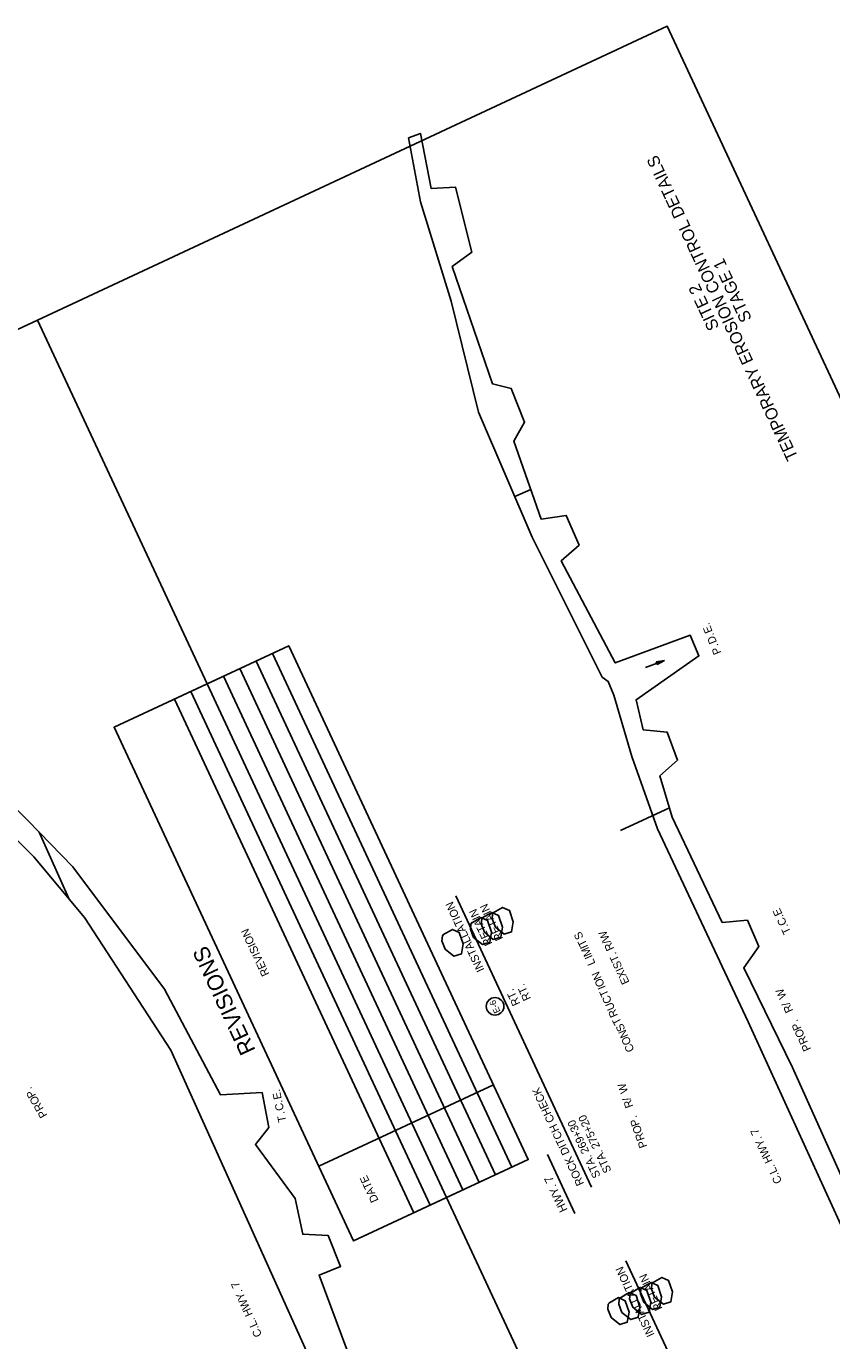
# Model space of a CAD drawing. Extents: x 964229 to 965790, y 1899262 to 1901149.
# Drawn here: x 964635 to 965239, y 1900163 to 1901149 of the extents above; entities that cross this region are included whole.
import ezdxf

# ---------------------------------------------------------------- set-up
doc = ezdxf.new("R2010")
doc.units = 0
for name, color, linetype in [('1', 7, 'Continuous'), ('43', 7, 'Continuous'), ('44', 7, 'Continuous'), ('60', 7, 'Continuous'), ('Default', 7, 'Continuous'), ('NO PLOT', 7, 'Continuous'), ('R_Draft', 7, 'Continuous'), ('R_Horz Alg Annot', 7, 'Continuous'), ('S_TREE', 7, 'Continuous')]:
    doc.layers.add(name, color=color, linetype=linetype)

msp = doc.modelspace()

# ---------------------------------------------------------------- linework, layer by layer
at = {"layer": '1'}
for p, q in [((964770.42, 1900655.58), (964643.21, 1900928.38)), ((965070.98, 1900011.03), (964950.03, 1900270.4))]:
    msp.add_line(p, q, dxfattribs=at)
msp.add_circle((964986.37, 1900413.77), 6.61, dxfattribs=at)
at = {"layer": '43'}
for p, q in [((965107.31, 1900672.01), (965113.37, 1900673.17)), ((965108.07, 1900670.01), (965107.31, 1900672.01)), ((965113.37, 1900673.17), (965108.07, 1900670.01))]:
    msp.add_line(p, q, dxfattribs=at)
msp.add_lwpolyline([(965099.17, 1900667.78), (965113.37, 1900673.17)], dxfattribs=at)
at = {"layer": '44'}
for p, q in [((965058.7, 1900278.13), (964956.85, 1900496.56)), ((965046.31, 1900258.35), (965025.67, 1900302.62)), ((965186.28, 1900004.53), (965084.43, 1900222.96))]:
    msp.add_line(p, q, dxfattribs=at)
at = {"layer": 'Default'}
for p, q in [((964700.63, 1900623.04), (964831.6, 1900684.11)), ((965011.21, 1900298.93), (964831.6, 1900684.11)), ((964986.74, 1900287.52), (964807.12, 1900672.7)), ((964998.97, 1900293.22), (964819.36, 1900678.4)), ((964962.27, 1900276.11), (964782.65, 1900661.29)), ((964962.27, 1900276.11), (964782.65, 1900661.29)), ((964974.5, 1900281.81), (964794.89, 1900666.99)), ((964950.03, 1900270.4), (964770.42, 1900655.58)), ((964925.56, 1900258.99), (964745.95, 1900644.17)), ((964937.8, 1900264.7), (964758.18, 1900649.88)), ((964880.25, 1900237.86), (964700.63, 1900623.04)), ((964854.12, 1900293.88), (964985.09, 1900354.95)), ((964880.25, 1900237.86), (965011.21, 1900298.93))]:
    msp.add_line(p, q, dxfattribs=at)
at = {"layer": 'NO PLOT'}
for points in [[(965789.77, 1899702.74), (965115.54, 1901148.63), (964643.21, 1900928.38), (964770.42, 1900655.58), (964831.6, 1900684.11), (965011.21, 1900298.93), (964950.03, 1900270.4), (965070.98, 1900011.03), (965126.95, 1900037.14), (965271.77, 1899726.58), (965215.79, 1899700.48), (965317.44, 1899482.49)], [(965789.77, 1899702.74), (965115.54, 1901148.63), (964643.21, 1900928.38), (964770.42, 1900655.58), (964831.6, 1900684.11), (965011.21, 1900298.93), (964950.03, 1900270.4), (965070.98, 1900011.03), (965126.95, 1900037.14), (965271.77, 1899726.58), (965215.79, 1899700.48), (965317.44, 1899482.49)], [(965789.77, 1899702.74), (965115.54, 1901148.63), (964643.21, 1900928.38), (964770.42, 1900655.58), (964831.6, 1900684.11), (965011.21, 1900298.93), (964950.03, 1900270.4), (965070.98, 1900011.03), (965126.95, 1900037.14), (965271.77, 1899726.58), (965215.79, 1899700.48), (965317.44, 1899482.49)], [(965789.77, 1899702.74), (965115.54, 1901148.63), (964643.21, 1900928.38), (964770.42, 1900655.58), (964831.6, 1900684.11), (965011.21, 1900298.93), (964950.03, 1900270.4), (965070.98, 1900011.03), (965126.95, 1900037.14), (965271.77, 1899726.58), (965215.79, 1899700.48), (965317.44, 1899482.49)], [(964845.11, 1899262.24), (964344.7, 1900335.36), (964389.48, 1900356.24), (964306.73, 1900533.69), (964319.96, 1900539.86), (964228.89, 1900735.17), (964643.21, 1900928.38), (964770.42, 1900655.58), (964700.63, 1900623.04), (964880.25, 1900237.86), (964950.03, 1900270.4), (965070.98, 1900011.03), (965017.24, 1899985.98), (965162.05, 1899675.42), (965215.79, 1899700.48), (965317.44, 1899482.49)], [(964845.11, 1899262.24), (964344.7, 1900335.36), (964389.48, 1900356.24), (964306.73, 1900533.69), (964319.96, 1900539.86), (964228.89, 1900735.17), (964643.21, 1900928.38), (964770.42, 1900655.58), (964700.63, 1900623.04), (964880.25, 1900237.86), (964950.03, 1900270.4), (965070.98, 1900011.03), (965017.24, 1899985.98), (965162.05, 1899675.42), (965215.79, 1899700.48), (965317.44, 1899482.49)], [(964845.11, 1899262.24), (964344.7, 1900335.36), (964389.48, 1900356.24), (964306.73, 1900533.69), (964319.96, 1900539.86), (964228.89, 1900735.17), (964643.21, 1900928.38), (964770.42, 1900655.58), (964700.63, 1900623.04), (964880.25, 1900237.86), (964950.03, 1900270.4), (965070.98, 1900011.03), (965017.24, 1899985.98), (965162.05, 1899675.42), (965215.79, 1899700.48), (965317.44, 1899482.49)], [(964845.11, 1899262.24), (964344.7, 1900335.36), (964389.48, 1900356.24), (964306.73, 1900533.69), (964319.96, 1900539.86), (964228.89, 1900735.17), (964643.21, 1900928.38), (964770.42, 1900655.58), (964700.63, 1900623.04), (964880.25, 1900237.86), (964950.03, 1900270.4), (965070.98, 1900011.03), (965017.24, 1899985.98), (965162.05, 1899675.42), (965215.79, 1899700.48), (965317.44, 1899482.49)]]:
    msp.add_lwpolyline(points, close=True, dxfattribs=at)
for points in [[(965276.22, 1900219.57), (965209.45, 1900368.04), (965172.94, 1900442.58), (965184.09, 1900458.7), (965175.64, 1900478.35), (965156.73, 1900476.57), (965119.19, 1900555.56), (965110.04, 1900586.51), (965123.23, 1900598.29), (965115.52, 1900619.35), (965097.43, 1900621.13), (965092.19, 1900643.69), (965139.24, 1900676.55), (965132.67, 1900692.15), (965076.52, 1900671.25), (965035.92, 1900747.75), (965049.39, 1900759.67), (965039.71, 1900781.92), (965020.92, 1900779.15), (965000.39, 1900837.54), (965008.5, 1900851.88), (964998.48, 1900877.15), (964984.57, 1900880.52), (964954.14, 1900968.46), (964968.86, 1900979.2), (964956.64, 1901028.08), (964938.47, 1901027), (964930.46, 1901068.35), (964921.51, 1901064.88), (964930.48, 1901016.94), (964953.57, 1900942.48), (964973.99, 1900859.39), (965014.26, 1900765.47), (965066.66, 1900660.66), (965071.22, 1900657.42), (965075.39, 1900647.12), (965088.99, 1900601.01), (965108.1, 1900546.87), (965176.25, 1900402.21), (965291.71, 1900149.32)], [(964559.33, 1900606.42), (964640.41, 1900525.78), (964678.6, 1900480.49), (964743.2, 1900380.79), (964921.35, 1899985.44)], [(964905.36, 1900075.22), (964854.38, 1900212.3), (964870.5, 1900218.78), (964861.28, 1900241.9), (964842.21, 1900242.83), (964836.44, 1900269.62), (964806.72, 1900310.07), (964816.72, 1900323.01), (964811.78, 1900349.15), (964780.47, 1900347.49), (964738.38, 1900426.65), (964669.78, 1900518.27), (964635.92, 1900553.17), (964585.88, 1900602.76)]]:
    msp.add_lwpolyline(points, dxfattribs=at)
at = {"layer": 'R_Horz Alg Annot'}
msp.add_line((964644.4, 1900544.42), (964666.65, 1900494.66), dxfattribs=at)
for points in [[(965001.15, 1900796.05), (965013.11, 1900801.36)], [(965080.56, 1900545.69), (965117.09, 1900562.69)]]:
    msp.add_lwpolyline(points, dxfattribs=at)
at = {"layer": 'S_TREE'}
for points in [[(964976.78, 1900480.04), (964983.92, 1900484.16), (964988.97, 1900481.86), (964991.88, 1900473.25), (964990.6, 1900465.73), (964985.03, 1900463.96), (964978.46, 1900469.3), (964976.05, 1900475.55), (964976.34, 1900479.25), (964977.42, 1900480.57)], [(964976.78, 1900480.04), (964983.92, 1900484.16), (964988.97, 1900481.86), (964991.88, 1900473.25), (964990.6, 1900465.73), (964985.03, 1900463.96), (964978.46, 1900469.3), (964976.05, 1900475.55), (964976.34, 1900479.25), (964977.42, 1900480.57)], [(964976.78, 1900480.04), (964983.92, 1900484.16), (964988.97, 1900481.86), (964991.88, 1900473.25), (964990.6, 1900465.73), (964985.03, 1900463.96), (964978.46, 1900469.3), (964976.05, 1900475.55), (964976.34, 1900479.25), (964977.42, 1900480.57)], [(964984.94, 1900483.84), (964992.08, 1900487.96), (964997.13, 1900485.66), (965000.04, 1900477.05), (964998.75, 1900469.53), (964993.18, 1900467.77), (964986.61, 1900473.1), (964984.2, 1900479.36), (964984.49, 1900483.05), (964985.58, 1900484.37)], [(964984.94, 1900483.84), (964992.08, 1900487.96), (964997.13, 1900485.66), (965000.04, 1900477.05), (964998.75, 1900469.53), (964993.18, 1900467.77), (964986.61, 1900473.1), (964984.2, 1900479.36), (964984.49, 1900483.05), (964985.58, 1900484.37)], [(964984.94, 1900483.84), (964992.08, 1900487.96), (964997.13, 1900485.66), (965000.04, 1900477.05), (964998.75, 1900469.53), (964993.18, 1900467.77), (964986.61, 1900473.1), (964984.2, 1900479.36), (964984.49, 1900483.05), (964985.58, 1900484.37)], [(964968.62, 1900476.23), (964975.77, 1900480.36), (964980.81, 1900478.05), (964983.72, 1900469.45), (964982.44, 1900461.92), (964976.87, 1900460.16), (964970.3, 1900465.49), (964967.89, 1900471.75), (964968.18, 1900475.45), (964969.26, 1900476.77)], [(964968.62, 1900476.23), (964975.77, 1900480.36), (964980.81, 1900478.05), (964983.72, 1900469.45), (964982.44, 1900461.92), (964976.87, 1900460.16), (964970.3, 1900465.49), (964967.89, 1900471.75), (964968.18, 1900475.45), (964969.26, 1900476.77)], [(964968.62, 1900476.23), (964975.77, 1900480.36), (964980.81, 1900478.05), (964983.72, 1900469.45), (964982.44, 1900461.92), (964976.87, 1900460.16), (964970.3, 1900465.49), (964967.89, 1900471.75), (964968.18, 1900475.45), (964969.26, 1900476.77)], [(964947.29, 1900467.36), (964954.43, 1900471.49), (964959.48, 1900469.19), (964962.39, 1900460.58), (964961.11, 1900453.06), (964955.53, 1900451.29), (964948.97, 1900456.62), (964946.55, 1900462.88), (964946.85, 1900466.58), (964947.93, 1900467.9)], [(964947.29, 1900467.36), (964954.43, 1900471.49), (964959.48, 1900469.19), (964962.39, 1900460.58), (964961.11, 1900453.06), (964955.53, 1900451.29), (964948.97, 1900456.62), (964946.55, 1900462.88), (964946.85, 1900466.58), (964947.93, 1900467.9)], [(965104.36, 1900206.44), (965111.5, 1900210.57), (965116.55, 1900208.26), (965119.46, 1900199.66), (965118.18, 1900192.13), (965112.61, 1900190.37), (965106.04, 1900195.7), (965103.62, 1900201.96), (965103.92, 1900205.65), (965105, 1900206.98)], [(965104.36, 1900206.44), (965111.5, 1900210.57), (965116.55, 1900208.26), (965119.46, 1900199.66), (965118.18, 1900192.13), (965112.61, 1900190.37), (965106.04, 1900195.7), (965103.62, 1900201.96), (965103.92, 1900205.65), (965105, 1900206.98)], [(965104.36, 1900206.44), (965111.5, 1900210.57), (965116.55, 1900208.26), (965119.46, 1900199.66), (965118.18, 1900192.13), (965112.61, 1900190.37), (965106.04, 1900195.7), (965103.62, 1900201.96), (965103.92, 1900205.65), (965105, 1900206.98)], [(965104.36, 1900206.44), (965111.5, 1900210.57), (965116.55, 1900208.26), (965119.46, 1900199.66), (965118.18, 1900192.13), (965112.61, 1900190.37), (965106.04, 1900195.7), (965103.62, 1900201.96), (965103.92, 1900205.65), (965105, 1900206.98)], [(965104.36, 1900206.44), (965111.5, 1900210.57), (965116.55, 1900208.26), (965119.46, 1900199.66), (965118.18, 1900192.13), (965112.61, 1900190.37), (965106.04, 1900195.7), (965103.62, 1900201.96), (965103.92, 1900205.65), (965105, 1900206.98)], [(965079.89, 1900195.03), (965087.03, 1900199.16), (965092.08, 1900196.85), (965094.99, 1900188.25), (965093.71, 1900180.72), (965088.14, 1900178.96), (965081.57, 1900184.29), (965079.15, 1900190.55), (965079.45, 1900194.24), (965080.53, 1900195.56)], [(965079.89, 1900195.03), (965087.03, 1900199.16), (965092.08, 1900196.85), (965094.99, 1900188.25), (965093.71, 1900180.72), (965088.14, 1900178.96), (965081.57, 1900184.29), (965079.15, 1900190.55), (965079.45, 1900194.24), (965080.53, 1900195.56)], [(965088.05, 1900198.83), (965095.19, 1900202.96), (965100.24, 1900200.66), (965103.15, 1900192.05), (965101.86, 1900184.53), (965096.29, 1900182.76), (965089.72, 1900188.09), (965087.31, 1900194.35), (965087.6, 1900198.05), (965088.69, 1900199.37)], [(965088.05, 1900198.83), (965095.19, 1900202.96), (965100.24, 1900200.66), (965103.15, 1900192.05), (965101.86, 1900184.53), (965096.29, 1900182.76), (965089.72, 1900188.09), (965087.31, 1900194.35), (965087.6, 1900198.05), (965088.69, 1900199.37)], [(965088.05, 1900198.83), (965095.19, 1900202.96), (965100.24, 1900200.66), (965103.15, 1900192.05), (965101.86, 1900184.53), (965096.29, 1900182.76), (965089.72, 1900188.09), (965087.31, 1900194.35), (965087.6, 1900198.05), (965088.69, 1900199.37)], [(965096.2, 1900202.64), (965103.34, 1900206.76), (965108.39, 1900204.46), (965111.3, 1900195.85), (965110.02, 1900188.33), (965104.45, 1900186.57), (965097.88, 1900191.9), (965095.47, 1900198.16), (965095.76, 1900201.85), (965096.84, 1900203.17)], [(965096.2, 1900202.64), (965103.34, 1900206.76), (965108.39, 1900204.46), (965111.3, 1900195.85), (965110.02, 1900188.33), (965104.45, 1900186.57), (965097.88, 1900191.9), (965095.47, 1900198.16), (965095.76, 1900201.85), (965096.84, 1900203.17)], [(965096.2, 1900202.64), (965103.34, 1900206.76), (965108.39, 1900204.46), (965111.3, 1900195.85), (965110.02, 1900188.33), (965104.45, 1900186.57), (965097.88, 1900191.9), (965095.47, 1900198.16), (965095.76, 1900201.85), (965096.84, 1900203.17)], [(965096.2, 1900202.64), (965103.34, 1900206.76), (965108.39, 1900204.46), (965111.3, 1900195.85), (965110.02, 1900188.33), (965104.45, 1900186.57), (965097.88, 1900191.9), (965095.47, 1900198.16), (965095.76, 1900201.85), (965096.84, 1900203.17)], [(965096.2, 1900202.64), (965103.34, 1900206.76), (965108.39, 1900204.46), (965111.3, 1900195.85), (965110.02, 1900188.33), (965104.45, 1900186.57), (965097.88, 1900191.9), (965095.47, 1900198.16), (965095.76, 1900201.85), (965096.84, 1900203.17)], [(965071.73, 1900191.23), (965078.87, 1900195.35), (965083.92, 1900193.05), (965086.83, 1900184.44), (965085.55, 1900176.92), (965079.98, 1900175.15), (965073.41, 1900180.49), (965071, 1900186.75), (965071.29, 1900190.44), (965072.37, 1900191.76)], [(965071.73, 1900191.23), (965078.87, 1900195.35), (965083.92, 1900193.05), (965086.83, 1900184.44), (965085.55, 1900176.92), (965079.98, 1900175.15), (965073.41, 1900180.49), (965071, 1900186.75), (965071.29, 1900190.44), (965072.37, 1900191.76)]]:
    msp.add_lwpolyline(points, dxfattribs=at)

# ---------------------------------------------------------------- texts
at = {"layer": '1'}
msp.add_text('E-6 ', height=4.8, rotation=115, dxfattribs=at).set_placement((964990.46, 1900409.94))
at = {"layer": '44'}
for s, height, p in [('INSTALLATION', 6, (964978.53, 1900441.17)), ('RETAIN', 6, (964984.47, 1900460.83)), ('RETAIN', 6, (964992.63, 1900464.63)), ('RT.', 6, (965005.28, 1900415.81)), ('RT.', 6, (965013.44, 1900419.62)), ('ROCK DITCH CHECK', 6, (965053.27, 1900280.89)), ('STA. 269+30', 6, (965065.66, 1900286.66)), ('STA. 275+20', 6, (965073.82, 1900290.47)), ('HWY. 7', 6.25, (965040.83, 1900261.15)), ('INSTALLATION', 6, (965106.11, 1900167.58)), ('RETAIN', 6, (965112.05, 1900187.24))]:
    msp.add_text(s, height=height, rotation=115, dxfattribs=at).set_placement(p)
at = {"layer": '60'}
for s, p in [('TEMPORARY EROSION CONTROL DETAILS', (965213.89, 1900825.49)), ('STAGE 1', (965179.13, 1900929.31)), ('SITE 2', (965154.75, 1900923.02))]:
    msp.add_text(s, height=9, rotation=115, dxfattribs=at).set_placement(p)
at = {"layer": 'Default'}
for s, height, p in [('REVISION', 6, (964817.27, 1900437.98)), ('REVISIONS', 12, (964806.95, 1900380.86)), ('DATE', 6, (964899.13, 1900268.34))]:
    msp.add_text(s, height=height, rotation=115, dxfattribs=at).set_placement(p)
at = {"layer": 'R_Draft'}
for s, rotation, p in [('.', 112.12609, (965147.67, 1900699.85)), ('E', 112.12609, (965149.69, 1900694.86)), ('D', 112.12609, (965152.93, 1900686.89)), ('.', 112.12609, (965150.8, 1900692.15)), ('P', 112.12609, (965156.17, 1900678.93)), ('.', 112.12609, (965154.04, 1900684.18)), ('T.C.E', 115, (965208.44, 1900469.43)), ('S', 117.12034, (965052.94, 1900465.61)), ('EXIST. R/W', 114.61604, (965087.31, 1900431.86)), ('T', 117.12034, (965055.61, 1900460.39)), ('I', 113.79739, (965056.32, 1900458.53)), ('M', 113.79739, (965058.91, 1900452.66)), ('I', 113.79739, (965059.71, 1900450.84)), ('L', 112.94772, (965061.78, 1900445.87)), ('N', 113.54319, (965066.42, 1900435.16)), ('O', 112.84239, (965068.7, 1900429.76)), ('I', 112.84239, (965069.47, 1900427.94)), ('T', 114.5564, (965071.83, 1900422.57)), ('W', 115.04656, (965205.19, 1900420.99)), ('C', 114.5564, (965074.18, 1900417.42)), ('U', 112.93512, (965076.49, 1900412.13)), ('/', 115.04656, (965207.67, 1900415.68)), ('R', 115.04656, (965210.07, 1900410.55)), ('R', 112.93512, (965078.7, 1900406.91)), ('T', 118.98374, (965081.54, 1900401.79)), ('S', 118.98374, (965084.29, 1900396.83)), ('N', 113.35986, (965086.4, 1900391.56)), ('P', 115.04656, (965216.25, 1900397.32)), ('O', 115.04656, (965218.73, 1900392.01)), ('.', 115.04656, (965213.85, 1900402.46)), ('O', 113.29064, (965088.72, 1900386.18)), ('C', 113.29064, (965090.96, 1900380.97)), ('R', 115.04656, (965221.13, 1900386.88)), ('P', 115.04656, (965223.53, 1900381.74)), ('P', 120.18332, (964642.23, 1900347.08)), ('.', 120.18332, (964639.38, 1900351.98)), ('O', 120.18332, (964645.18, 1900342.01)), ('E', 101.39373, (964826.39, 1900344.56)), ('.', 101.39373, (964825.33, 1900349.84)), ('W', 109.23994, (965086.28, 1900349.63)), ('R', 120.18332, (964648.03, 1900337.11)), ('C', 101.39373, (964828.09, 1900336.13)), ('.', 101.39373, (964826.97, 1900341.69)), ('/', 109.23994, (965088.21, 1900344.1)), ('R', 109.23994, (965090.08, 1900338.74)), ('P', 120.18332, (964650.88, 1900332.21)), ('T', 101.39373, (964829.83, 1900327.52)), ('.', 101.39373, (964828.67, 1900333.26)), ('P', 109.23994, (965094.89, 1900324.96)), ('.', 109.23994, (965093.03, 1900330.31)), ('O', 109.23994, (965096.82, 1900319.43)), ('R', 109.23994, (965098.69, 1900314.08)), ('C.L. HWY. 7', 114.85745, (965201.75, 1900282.39)), ('P', 109.23994, (965100.56, 1900308.73)), ('C.L. HWY. 7', 114.01559, (964811.73, 1900167.32))]:
    msp.add_text(s, height=6, rotation=rotation, dxfattribs=at).set_placement(p)

doc.saveas('drawing.dxf')
